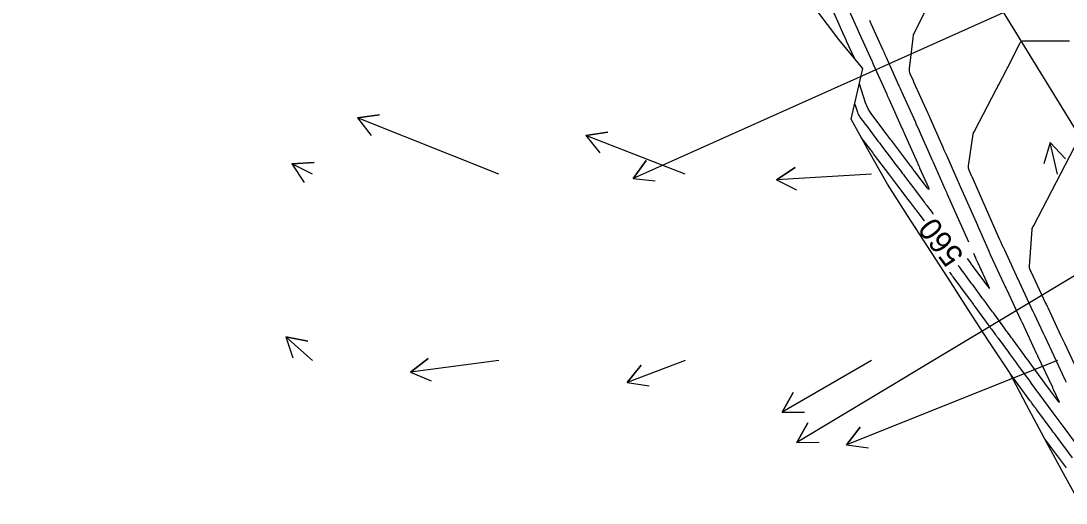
# Model space of a CAD drawing. Extents: x 954385 to 988206, y 1868364 to 1924553.
# Drawn here: x 956878.8 to 957159.4, y 1920780.6 to 1920910.1 of the extents above; entities that cross this region are included whole.
import ezdxf

# ---------------------------------------------------------------- set-up
doc = ezdxf.new("R2010")
doc.units = 0
for name, color, linetype in [('Default', 7, 'Continuous'), ('Ex_Contour Labels', 7, 'Continuous'), ('Ex_Major Contours', 7, 'Continuous'), ('Ex_Minor Contours', 7, 'Continuous'), ('Perimeter', 7, 'Continuous'), ('Slopes', 7, 'Continuous')]:
    doc.layers.add(name, color=color, linetype=linetype)

msp = doc.modelspace()

# ---------------------------------------------------------------- linework, layer by layer
at = {"layer": 'Default'}
msp.add_line((957221.14, 1920784.24), (956045.8, 1922705.18), dxfattribs=at)
at = {"layer": 'Ex_Major Contours'}
for points in [[(957125.98, 1920921.71), (957118.38, 1920906.33), (957118.36, 1920906.29), (957118.35, 1920906.26), (957118.34, 1920906.22), (957118.34, 1920906.19), (957118.27, 1920905.68), (957118.26, 1920905.58), (957118.25, 1920905.48), (957117.28, 1920897.39), (957117.26, 1920897.02), (957117.29, 1920896.67), (957117.37, 1920896.32), (957117.49, 1920895.98), (957118.33, 1920894.13), (957118.37, 1920894.04), (957118.41, 1920893.95), (957118.45, 1920893.86), (957118.49, 1920893.77), (957122.17, 1920885.56), (957122.35, 1920885.15), (957122.53, 1920884.75), (957122.71, 1920884.34), (957122.89, 1920883.93), (957125.96, 1920877), (957126.29, 1920876.26), (957126.62, 1920875.52), (957126.94, 1920874.78), (957127.27, 1920874.05), (957130.33, 1920867.13), (957130.52, 1920866.71), (957130.7, 1920866.3), (957130.89, 1920865.88), (957131.07, 1920865.47), (957135.59, 1920855.25), (957136, 1920854.33), (957136.13, 1920854.03), (957138.68, 1920848.27), (957138.77, 1920848.06), (957138.87, 1920847.85), (957138.97, 1920847.64), (957139.06, 1920847.43), (957142.72, 1920839.55), (957142.91, 1920839.13), (957143.1, 1920838.72), (957143.3, 1920838.3), (957143.49, 1920837.89), (957147.21, 1920829.94), (957147.29, 1920829.77), (957147.37, 1920829.6), (957147.45, 1920829.44), (957147.53, 1920829.27), (957151.51, 1920820.76), (957151.57, 1920820.62), (957151.63, 1920820.49), (957151.7, 1920820.36), (957151.76, 1920820.22), (957155.73, 1920811.75), (957155.81, 1920811.56), (957155.9, 1920811.38), (957155.99, 1920811.19), (957156.07, 1920811.01), (957157.47, 1920807.99), (957157.57, 1920807.74), (957157.58, 1920807.65), (957157.51, 1920807.71), (957157.34, 1920807.91), (957155.22, 1920810.78), (957155.18, 1920810.84), (957155.13, 1920810.91), (957155.09, 1920810.97), (957155.04, 1920811.03), (957154.68, 1920811.53), (957150.3, 1920817.5), (957149.75, 1920818.25), (957149.2, 1920819), (957148.65, 1920819.75), (957148.1, 1920820.5), (957145.18, 1920824.48), (957144.99, 1920824.74), (957144.8, 1920825), (957144.61, 1920825.26), (957144.41, 1920825.52), (957143.65, 1920826.57), (957143.45, 1920826.83), (957143.26, 1920827.09), (957143.07, 1920827.35), (957142.88, 1920827.61), (957139.89, 1920831.69), (957139.64, 1920832.04), (957139.38, 1920832.39), (957139.12, 1920832.74), (957138.87, 1920833.09), (957137.84, 1920834.48), (957137.59, 1920834.83), (957137.33, 1920835.18), (957137.07, 1920835.53), (957136.81, 1920835.88), (957134.62, 1920838.86), (957134.29, 1920839.3), (957133.97, 1920839.74), (957133.64, 1920840.18), (957133.32, 1920840.62), (957132.02, 1920842.38), (957131.7, 1920842.82), (957131.37, 1920843.26), (957131.04, 1920843.7), (957130.71, 1920844.13), (957130.45, 1920844.47)], [(957121.39, 1920856.43), (957119.67, 1920858.7), (957119.45, 1920858.99), (957119.23, 1920859.28), (957119.01, 1920859.57), (957118.79, 1920859.86), (957117.69, 1920861.31), (957117.03, 1920862.19), (957114.24, 1920865.87), (957113.7, 1920866.58), (957113.16, 1920867.29), (957112.62, 1920868), (957112.08, 1920868.71), (957107.75, 1920874.42), (957107.62, 1920874.6), (957107.49, 1920874.77), (957107.22, 1920875.12), (957107.16, 1920875.21), (957107.09, 1920875.3), (957107.02, 1920875.39), (957106.96, 1920875.47), (957104.41, 1920878.86)]]:
    msp.add_lwpolyline(points, dxfattribs=at)
at = {"layer": 'Ex_Minor Contours'}
for points in [[(957099.49, 1920916.65), (957103.27, 1920908.23), (957103.31, 1920908.15), (957103.34, 1920908.08), (957103.89, 1920906.85), (957107.23, 1920899.44), (957107.33, 1920899.2), (957107.44, 1920898.96), (957107.55, 1920898.72), (957107.66, 1920898.48), (957111.26, 1920890.48), (957111.42, 1920890.13), (957111.58, 1920889.77), (957111.74, 1920889.42), (957111.9, 1920889.06), (957115.44, 1920881.17), (957115.57, 1920880.87), (957115.71, 1920880.57), (957115.84, 1920880.27), (957115.97, 1920879.98), (957119.49, 1920872.03), (957119.64, 1920871.69), (957119.79, 1920871.35), (957119.94, 1920871), (957120.09, 1920870.66), (957122.44, 1920865.37), (957122.6, 1920864.97), (957122.61, 1920864.81), (957122.48, 1920864.9), (957122.21, 1920865.24), (957118.82, 1920869.7), (957118.4, 1920870.26), (957118.28, 1920870.42), (957118.16, 1920870.58), (957117.81, 1920871.04), (957117.66, 1920871.24), (957117.5, 1920871.45), (957112.59, 1920877.92), (957112.4, 1920878.18), (957112.21, 1920878.43), (957112.02, 1920878.68), (957111.83, 1920878.94), (957111.06, 1920879.95), (957110.68, 1920880.46), (957110.3, 1920880.97), (957107.24, 1920885.03), (957106.74, 1920885.76), (957106.29, 1920886.52), (957105.92, 1920887.32), (957105.6, 1920888.15), (957103.91, 1920893.22)], [(957102.57, 1920900.13), (957100.5, 1920904.72), (957100.47, 1920904.79), (957100.41, 1920904.92), (957100.4, 1920904.94), (957099.92, 1920906), (957099.88, 1920906.1), (957099.86, 1920906.14), (957096.04, 1920914.64)], [(957133.28, 1920850.69), (957127.61, 1920863.48), (957127.45, 1920863.85), (957127.29, 1920864.21), (957127.13, 1920864.58), (957126.97, 1920864.94), (957123.78, 1920872.13), (957123.49, 1920872.78), (957123.2, 1920873.43), (957122.91, 1920874.09), (957122.63, 1920874.74), (957120.44, 1920879.68), (957120.04, 1920880.57), (957119.19, 1920882.49), (957119.16, 1920882.58), (957119.12, 1920882.66), (957119.08, 1920882.74), (957119.04, 1920882.83), (957115.35, 1920891.07), (957115.17, 1920891.46), (957115, 1920891.86), (957114.82, 1920892.25), (957114.64, 1920892.65), (957111.49, 1920899.64), (957111.17, 1920900.35), (957110.86, 1920901.05), (957110.54, 1920901.75), (957110.22, 1920902.45), (957107.12, 1920909.35), (957106.92, 1920909.79), (957106.72, 1920910.24)], [(957159.47, 1920813.13), (957159.31, 1920813.46), (957159.16, 1920813.8), (957159, 1920814.13), (957155.12, 1920822.41), (957155.05, 1920822.58), (957154.97, 1920822.74), (957153.78, 1920825.28), (957153.37, 1920826.16), (957150.95, 1920831.34), (957150.86, 1920831.52), (957150.78, 1920831.69), (957150.7, 1920831.87), (957150.62, 1920832.04), (957146.93, 1920839.93), (957146.72, 1920840.37), (957146.52, 1920840.81), (957146.31, 1920841.24), (957146.11, 1920841.68), (957142.93, 1920848.53), (957142.61, 1920849.24), (957142.29, 1920849.94), (957141.97, 1920850.64), (957141.65, 1920851.35), (957134.18, 1920868.23), (957134.11, 1920868.39), (957134.04, 1920868.54), (957133.38, 1920870.03), (957133.28, 1920870.31), (957133.22, 1920870.59), (957133.2, 1920870.88), (957133.23, 1920871.17), (957134.46, 1920879.69), (957134.48, 1920879.78), (957134.5, 1920879.87), (957134.53, 1920879.96), (957134.57, 1920880.05), (957134.75, 1920880.38), (957134.79, 1920880.47), (957134.84, 1920880.55), (957134.88, 1920880.64), (957134.92, 1920880.72), (957140.66, 1920891.72), (957140.81, 1920892), (957140.96, 1920892.29), (957141.11, 1920892.58), (957141.26, 1920892.86), (957143.4, 1920896.98), (957143.61, 1920897.37), (957143.82, 1920897.77), (957144.02, 1920898.17), (957144.22, 1920898.58), (957146.98, 1920904.07), (957147.2, 1920904.4), (957147.47, 1920904.64), (957147.81, 1920904.78), (957148.2, 1920904.82), (957153.7, 1920904.78), (957154.48, 1920904.77), (957155.25, 1920904.77), (957156.02, 1920904.77), (957156.79, 1920904.78), (957160.34, 1920904.81)], [(957102.66, 1920887.74), (957103.37, 1920885.61), (957103.5, 1920885.26), (957103.66, 1920884.92), (957103.85, 1920884.6), (957104.06, 1920884.29), (957105.04, 1920883), (957105.51, 1920882.36), (957105.99, 1920881.73), (957108.91, 1920877.85), (957109.28, 1920877.36), (957109.65, 1920876.87), (957110.02, 1920876.37), (957110.4, 1920875.88), (957111.89, 1920873.91), (957112.27, 1920873.41), (957112.64, 1920872.92), (957113.01, 1920872.43), (957113.39, 1920871.93), (957115.12, 1920869.65), (957115.42, 1920869.25), (957115.72, 1920868.86), (957116.02, 1920868.46), (957116.32, 1920868.07), (957117.82, 1920866.09), (957118.42, 1920865.3), (957118.72, 1920864.9), (957121.34, 1920861.44), (957121.56, 1920861.14), (957121.79, 1920860.85), (957122.02, 1920860.55), (957122.24, 1920860.25), (957123.15, 1920859.05), (957123.38, 1920858.75), (957123.6, 1920858.45), (957123.77, 1920858.23)], [(957162.75, 1920878.35), (957150.64, 1920855.12), (957150.61, 1920855.07), (957150.58, 1920855.01), (957150.55, 1920854.96), (957150.53, 1920854.9), (957150.25, 1920854.27), (957150.23, 1920854.23), (957150.22, 1920854.18), (957150.21, 1920854.13), (957150.2, 1920854.08), (957149.46, 1920844.23), (957149.46, 1920844.08), (957149.48, 1920843.94), (957149.51, 1920843.81), (957149.56, 1920843.68), (957149.9, 1920842.95), (957149.91, 1920842.92), (957149.93, 1920842.89), (957149.94, 1920842.86), (957149.96, 1920842.83), (957153.92, 1920834.36), (957154.06, 1920834.07), (957154.19, 1920833.78), (957154.33, 1920833.49), (957154.47, 1920833.2), (957157.94, 1920825.77), (957158.2, 1920825.22), (957158.46, 1920824.67), (957158.72, 1920824.11), (957158.98, 1920823.56), (957162.18, 1920816.73)], [(957119.01, 1920854.62), (957118.65, 1920855.1)], [(957132.83, 1920846.28), (957133.8, 1920845.01), (957133.87, 1920844.92), (957133.93, 1920844.83), (957134, 1920844.74), (957134.06, 1920844.65), (957134.53, 1920844.02), (957134.59, 1920843.93), (957138.37, 1920838.81), (957138.7, 1920838.4), (957138.85, 1920838.28), (957138.82, 1920838.47), (957138.61, 1920838.96), (957135.77, 1920845.09), (957135.61, 1920845.42), (957135.46, 1920845.76), (957135.31, 1920846.1), (957135.15, 1920846.44), (957134.62, 1920847.64)], [(957128.08, 1920842.67), (957128.11, 1920842.63), (957128.61, 1920841.96), (957128.71, 1920841.83), (957128.81, 1920841.7), (957128.91, 1920841.56), (957129.01, 1920841.43), (957133.15, 1920835.81), (957133.48, 1920835.37), (957133.8, 1920834.93), (957134.45, 1920834.06), (957134.61, 1920833.84), (957134.77, 1920833.62), (957134.93, 1920833.4), (957135.09, 1920833.18), (957138.5, 1920828.53), (957138.72, 1920828.23), (957138.94, 1920827.93), (957139.16, 1920827.63), (957139.38, 1920827.33), (957140.26, 1920826.13), (957140.48, 1920825.83), (957140.7, 1920825.53), (957140.92, 1920825.23), (957141.14, 1920824.93), (957143.93, 1920821.13), (957144.2, 1920820.76), (957144.47, 1920820.39), (957144.74, 1920820.02), (957145.01, 1920819.65), (957146.1, 1920818.17), (957146.37, 1920817.8), (957146.64, 1920817.43), (957146.91, 1920817.06), (957147.18, 1920816.69), (957148.7, 1920814.62), (957149.04, 1920814.16), (957149.39, 1920813.69), (957149.73, 1920813.22), (957150.07, 1920812.75), (957151.78, 1920810.43), (957152.17, 1920809.88), (957152.57, 1920809.34), (957152.97, 1920808.8), (957153.37, 1920808.26), (957155.85, 1920804.91), (957156.12, 1920804.54), (957156.39, 1920804.18), (957156.66, 1920803.82), (957156.93, 1920803.45), (957158, 1920802), (957158.27, 1920801.63), (957158.54, 1920801.27), (957158.81, 1920800.91), (957159.08, 1920800.54), (957163.12, 1920795.14)], [(957161.18, 1920792.74), (957158.9, 1920795.8), (957158.02, 1920796.97), (957156.57, 1920798.92), (957156.27, 1920799.31), (957155.98, 1920799.7), (957155.69, 1920800.1), (957155.4, 1920800.49), (957151.57, 1920805.68), (957151.41, 1920805.89), (957151.26, 1920806.1), (957151.1, 1920806.31), (957150.95, 1920806.52), (957150.32, 1920807.36), (957150.17, 1920807.57), (957150.01, 1920807.78), (957149.86, 1920807.99), (957149.71, 1920808.2), (957144.4, 1920815.44)], [(957153.81, 1920797.62), (957159.18, 1920790.42), (957159.31, 1920790.26), (957159.43, 1920790.09)]]:
    msp.add_lwpolyline(points, dxfattribs=at)
at = {"layer": 'Perimeter'}
msp.add_lwpolyline([(957163.12, 1920780.62), (957158.31, 1920789.4), (957153.5, 1920798.19), (957148.78, 1920807.02), (957144.15, 1920815.91), (957138.58, 1920824.23), (957133.17, 1920832.64), (957127.8, 1920841.08), (957122.33, 1920849.45), (957116.87, 1920857.84), (957111.47, 1920866.26), (957106.54, 1920874.96), (957101.74, 1920883.75), (957104.85, 1920897.38), (957098.4, 1920905.15), (957092.36, 1920913.18)], dxfattribs=at)
at = {"layer": 'Slopes'}
for points in [[(957157.13, 1920918.93), (957043.17, 1920867.81), (957046.68, 1920872.67), (957043.17, 1920867.81), (957049.13, 1920867.2)], [(957007.13, 1920868.93), (956969.15, 1920884.07), (956975.09, 1920884.93), (956969.15, 1920884.07), (956972.87, 1920879.36)], [(957057.13, 1920868.93), (957030.49, 1920879.36), (957036.42, 1920880.26), (957030.49, 1920879.36), (957034.23, 1920874.67)], [(957157.13, 1920868.93), (957155.14, 1920877.47), (957159.24, 1920873.09), (957155.14, 1920877.47), (957153.4, 1920871.73)], [(956957.13, 1920868.93), (956951.55, 1920871.78), (956957.54, 1920872.09), (956951.55, 1920871.78), (956954.81, 1920866.74)], [(957107.13, 1920868.93), (957081.65, 1920867.47), (957086.66, 1920870.76), (957081.65, 1920867.47), (957087, 1920864.77)], [(957207.13, 1920868.93), (957087.13, 1920796.9), (957090.04, 1920802.14), (957087.13, 1920796.9), (957093.13, 1920797)], [(956957.13, 1920818.93), (956949.95, 1920825.3), (956955.83, 1920824.09), (956949.95, 1920825.3), (956951.85, 1920819.6)], [(957007.13, 1920818.93), (956983.42, 1920815.77), (956988.18, 1920819.43), (956983.42, 1920815.77), (956988.97, 1920813.48)], [(957057.13, 1920818.93), (957041.56, 1920813.05), (957045.36, 1920817.69), (957041.56, 1920813.05), (957047.48, 1920812.08)], [(957107.13, 1920818.93), (957083.18, 1920805.09), (957086.18, 1920810.29), (957083.18, 1920805.09), (957089.18, 1920805.09)], [(957157.13, 1920818.93), (957100.44, 1920796.32), (957104.15, 1920801.03), (957100.44, 1920796.32), (957106.38, 1920795.46)]]:
    msp.add_lwpolyline(points, dxfattribs=at)

# ---------------------------------------------------------------- texts
at = {"layer": 'Ex_Contour Labels'}
msp.add_text('560', height=6, rotation=127.1657, dxfattribs=at).set_placement((957132.2, 1920847.14))

doc.saveas('drawing.dxf')
